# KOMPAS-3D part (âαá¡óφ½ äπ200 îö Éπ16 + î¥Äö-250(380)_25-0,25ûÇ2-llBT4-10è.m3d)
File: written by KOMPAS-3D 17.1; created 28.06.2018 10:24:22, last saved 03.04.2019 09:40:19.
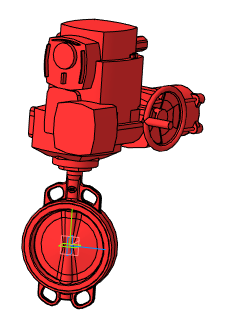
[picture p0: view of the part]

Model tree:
1. Операция без истории:2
